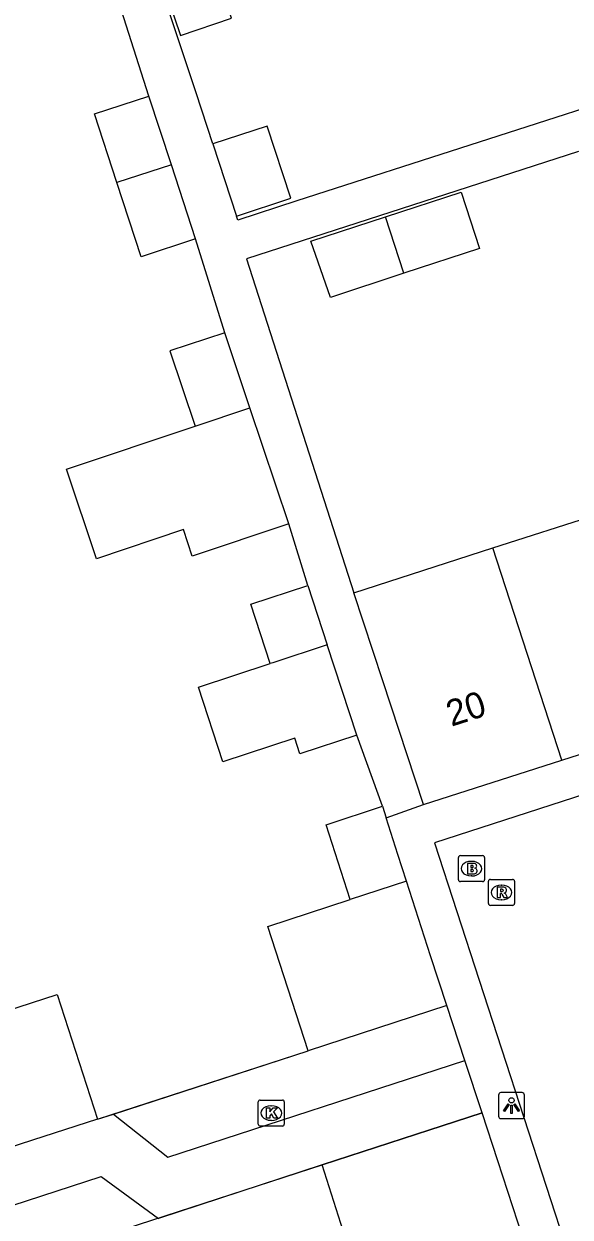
# Model space of a CAD drawing. Extents: x 159377 to 159983, y 382996 to 383595.
# Drawn here: x 159478 to 159498.96, y 383184.26 to 383230.07 of the extents above; entities that cross this region are included whole.
import ezdxf

# ---------------------------------------------------------------- set-up
doc = ezdxf.new("R2010")
doc.units = 0
for name, color, linetype in [('IMGEO_Brandkraan', 7, 'Continuous'), ('IMGEO_Groenvoorziening', 7, 'Continuous'), ('IMGEO_Kolk', 7, 'Continuous'), ('IMGEO_Lichtpunt', 7, 'Continuous'), ('IMGEO_Muur', 7, 'Continuous'), ('IMGEO_Pand', 7, 'Continuous'), ('IMGEO_Pand_nummerreeks', 7, 'Continuous'), ('IMGEO_Rijbaan_lokaal_open', 7, 'Continuous'), ('IMGEO_Rioolput', 7, 'Continuous'), ('IMGEO_Voetpad_open', 7, 'Continuous')]:
    doc.layers.add(name, color=color, linetype=linetype)

msp = doc.modelspace()

# ---------------------------------------------------------------- linework, layer by layer
at = {"layer": 'IMGEO_Brandkraan'}
for p, q in [((159494.749, 383198.14), (159495.601, 383198.14)), ((159494.674, 383197.214), (159494.674, 383198.066)), ((159495.162, 383197.92), (159495.187, 383197.92)), ((159495.675, 383198.066), (159495.675, 383197.214)), ((159495.185, 383197.36), (159495.16, 383197.36)), ((159495.601, 383197.14), (159494.749, 383197.14))]:
    msp.add_line(p, q, dxfattribs=at)
for points in [[(159494.749, 383198.14), (159495.601, 383198.14)], [(159494.674, 383197.214), (159494.674, 383198.066)], [(159495.022, 383197.84), (159495.022, 383197.44), (159495.235, 383197.44)], [(159495.253, 383197.84), (159495.022, 383197.84)], [(159495.201, 383197.759), (159495.147, 383197.759), (159495.147, 383197.683)], [(159495.147, 383197.683), (159495.2, 383197.683)], [(159495.675, 383198.066), (159495.675, 383197.214)], [(159495.209, 383197.607), (159495.147, 383197.607), (159495.147, 383197.526)], [(159495.147, 383197.526), (159495.209, 383197.526)], [(159495.601, 383197.14), (159494.749, 383197.14)]]:
    msp.add_lwpolyline(points, dxfattribs=at)
for centre, radius, start, end in [((159494.751, 383198.064), 0.0765, 91.552, 178.448), ((159494.751, 383198.064), 0.0765, 91.552, 178.448), ((159495.599, 383198.064), 0.0765, 1.552, 88.448), ((159495.599, 383198.064), 0.0765, 1.552, 88.448), ((159495.202, 383197.721), 0.0379, 267.8285, 90.9355), ((159495.257, 383197.695), 0.145, 59.4692, 91.5367), ((159495.282, 383197.742), 0.0922, 285.5137, 58.1501), ((159495.21, 383197.566), 0.0404, 269.8759, 90.5077), ((159495.241, 383197.691), 0.251, 268.6676, 293.5347), ((159495.287, 383197.55), 0.105, 301.3115, 78.989), ((159494.751, 383197.216), 0.0765, 181.552, 268.448), ((159494.751, 383197.216), 0.0765, 181.552, 268.448), ((159495.599, 383197.216), 0.0765, 271.552, 358.448), ((159495.599, 383197.216), 0.0765, 271.552, 358.448)]:
    msp.add_arc(centre, radius, start, end, dxfattribs=at)
for centre, major_axis, ratio, start_param, end_param in [((159495.161, 383197.64), (-0.387, 0.002), 0.722429, 4.712389, 7.853982), ((159495.186, 383197.64), (-0.39, 0.002), 0.717154, 1.570796, 4.712389)]:
    msp.add_ellipse(centre, major_axis=major_axis, ratio=ratio, start_param=start_param, end_param=end_param, dxfattribs=at)
at = {"layer": 'IMGEO_Groenvoorziening'}
msp.add_lwpolyline([(159481.432, 383188.219), (159488.903, 383190.64)], dxfattribs=at)
at = {"layer": 'IMGEO_Kolk'}
for p, q in [((159486.991, 383187.83), (159486.991, 383188.682)), ((159487.066, 383188.756), (159487.918, 383188.756)), ((159487.479, 383188.536), (159487.504, 383188.536)), ((159487.992, 383188.682), (159487.992, 383187.83)), ((159487.918, 383187.756), (159487.066, 383187.756)), ((159487.502, 383187.976), (159487.477, 383187.976))]:
    msp.add_line(p, q, dxfattribs=at)
for points in [[(159486.991, 383187.83), (159486.991, 383188.682)], [(159487.066, 383188.756), (159487.918, 383188.756)], [(159487.992, 383188.682), (159487.992, 383187.83)], [(159487.312, 383188.456), (159487.435, 383188.456), (159487.435, 383188.305), (159487.565, 383188.456), (159487.729, 383188.456), (159487.583, 383188.305), (159487.736, 383188.056), (159487.584, 383188.056), (159487.499, 383188.22), (159487.435, 383188.153), (159487.435, 383188.056), (159487.312, 383188.056), (159487.312, 383188.456)], [(159487.918, 383187.756), (159487.066, 383187.756)]]:
    msp.add_lwpolyline(points, dxfattribs=at)
for centre, start, end in [((159487.068, 383188.68), 91.552, 178.448), ((159487.068, 383188.68), 91.552, 178.448), ((159487.916, 383188.68), 1.552, 88.448), ((159487.916, 383188.68), 1.552, 88.448), ((159487.068, 383187.832), 181.552, 268.448), ((159487.068, 383187.832), 181.552, 268.448), ((159487.916, 383187.832), 271.552, 358.448), ((159487.916, 383187.832), 271.552, 358.448)]:
    msp.add_arc(centre, 0.0765, start, end, dxfattribs=at)
for centre, major_axis, ratio, start_param, end_param in [((159487.478, 383188.256), (-0.387, 0.002), 0.722429, 4.712389, 7.853982), ((159487.503, 383188.256), (-0.39, 0.002), 0.717154, 1.570796, 4.712389)]:
    msp.add_ellipse(centre, major_axis=major_axis, ratio=ratio, start_param=start_param, end_param=end_param, dxfattribs=at)
at = {"layer": 'IMGEO_Lichtpunt'}
for p, q in [((159497.113, 383189.041), (159496.305, 383189.041)), ((159497.113, 383189.041), (159496.305, 383189.041)), ((159496.211, 383188.946), (159496.211, 383188.139)), ((159496.211, 383188.946), (159496.211, 383188.139)), ((159497.207, 383188.139), (159497.207, 383188.946)), ((159497.207, 383188.139), (159497.207, 383188.946)), ((159496.305, 383188.045), (159497.113, 383188.045)), ((159496.305, 383188.045), (159497.113, 383188.045))]:
    msp.add_line(p, q, dxfattribs=at)
for points in [[(159496.585, 383188.61), (159496.624, 383188.582), (159496.436, 383188.32), (159496.398, 383188.347), (159496.585, 383188.61)], [(159496.687, 383188.562), (159496.734, 383188.562), (159496.734, 383188.24), (159496.687, 383188.24), (159496.687, 383188.562)], [(159496.797, 383188.582), (159496.835, 383188.609), (159497.022, 383188.347), (159496.983, 383188.319), (159496.797, 383188.582)]]:
    msp.add_lwpolyline(points, dxfattribs=at)
msp.add_circle((159496.71, 383188.744), 0.0994, dxfattribs=at)
for centre, start, end in [((159496.305, 383188.946), 90, 180), ((159496.305, 383188.946), 90, 180), ((159497.113, 383188.946), 0, 90), ((159497.113, 383188.946), 0, 90), ((159496.305, 383188.139), 180, 270), ((159496.305, 383188.139), 180, 270), ((159497.113, 383188.139), 270, 0), ((159497.113, 383188.139), 270, 360)]:
    msp.add_arc(centre, 0.0946, start, end, dxfattribs=at)
at = {"layer": 'IMGEO_Muur'}
for points in [[(159480.817, 383188.02), (159488.903, 383190.64)], [(159479.701, 383183.1), (159482.401, 383183.978), (159495.589, 383188.265)]]:
    msp.add_lwpolyline(points, dxfattribs=at)
at = {"layer": 'IMGEO_Pand'}
for points in [[(159482.871, 383232.987), (159484.01, 383229.627), (159485.967, 383230.29), (159484.837, 383233.623)], [(159481.567, 383223.976), (159480.704, 383226.615), (159482.795, 383227.299)], [(159483.659, 383224.654), (159482.795, 383227.299)], [(159486.157, 383222.692), (159488.238, 383223.375), (159487.33, 383226.144), (159485.248, 383225.462)], [(159485.248, 383225.462), (159486.157, 383222.692)], [(159483.659, 383224.654), (159481.567, 383223.976)], [(159484.587, 383221.813), (159483.659, 383224.654)], [(159484.587, 383221.813), (159482.497, 383221.131), (159481.567, 383223.976)], [(159491.878, 383222.663), (159494.778, 383223.614), (159495.481, 383221.446), (159492.581, 383220.495)], [(159492.581, 383220.495), (159489.763, 383219.571), (159489.015, 383221.724), (159491.878, 383222.663)], [(159492.581, 383220.495), (159491.878, 383222.663)], [(159485.703, 383218.216), (159483.604, 383217.513), (159484.57, 383214.627)], [(159486.67, 383215.33), (159485.703, 383218.216)], [(159484.57, 383214.627), (159486.67, 383215.33)], [(159488.161, 383210.876), (159486.67, 383215.33)], [(159488.161, 383210.876), (159484.461, 383209.638), (159484.12, 383210.655), (159480.784, 383209.538), (159479.633, 383212.974), (159484.57, 383214.627)], [(159495.999, 383209.952), (159500, 383211.241), (159501.129, 383211.604)], [(159490.664, 383208.234), (159495.999, 383209.952)], [(159498.642, 383201.8), (159495.999, 383209.952)], [(159487.453, 383205.513), (159486.706, 383207.787), (159488.894, 383208.506)], [(159488.894, 383208.506), (159489.641, 383206.231)], [(159493.339, 383200.096), (159491.778, 383204.846), (159490.664, 383208.234)], [(159489.641, 383206.231), (159487.545, 383205.542), (159487.453, 383205.513)], [(159490.78, 383202.765), (159489.641, 383206.231)], [(159490.78, 383202.765), (159488.592, 383202.046), (159488.395, 383202.646), (159485.637, 383201.74), (159484.695, 383204.606), (159487.453, 383205.513)], [(159498.642, 383201.8), (159500, 383202.236), (159503.773, 383203.448)], [(159493.339, 383200.096), (159498.642, 383201.8)], [(159490.525, 383196.453), (159489.601, 383199.327), (159491.758, 383200.033)], [(159491.758, 383200.033), (159491.9, 383199.592)], [(159492.685, 383197.153), (159492.353, 383198.185), (159491.9, 383199.592)], [(159492.685, 383197.153), (159490.525, 383196.453)], [(159494.222, 383192.386), (159493.605, 383194.291), (159492.685, 383197.153)], [(159488.903, 383190.64), (159487.357, 383195.413), (159490.525, 383196.453)], [(159476.779, 383191.997), (159479.269, 383192.804), (159480.817, 383188.02)], [(159494.222, 383192.386), (159488.903, 383190.64)], [(159495.589, 383188.265), (159489.44, 383186.266)], [(159497.142, 383183.482), (159496.188, 383186.42), (159495.589, 383188.265)], [(159480.817, 383188.02), (159478.331, 383187.21), (159469.497, 383184.351)], [(159494.955, 383182.771), (159490.967, 383181.485), (159489.44, 383186.266)]]:
    msp.add_lwpolyline(points, dxfattribs=at)
at = {"layer": 'IMGEO_Rijbaan_lokaal_open'}
msp.add_lwpolyline([(159520.354, 383207.214), (159514.946, 383205.47), (159500, 383200.651), (159493.749, 383198.635), (159499.75, 383180.18), (159500, 383180.243), (159536.251, 383191.843)], dxfattribs=at)
at = {"layer": 'IMGEO_Rioolput'}
for p, q in [((159495.899, 383197.227), (159496.751, 383197.227)), ((159495.824, 383196.301), (159495.824, 383197.153)), ((159496.312, 383197.007), (159496.337, 383197.007)), ((159496.825, 383197.153), (159496.825, 383196.301)), ((159496.335, 383196.447), (159496.31, 383196.447)), ((159496.751, 383196.227), (159495.899, 383196.227))]:
    msp.add_line(p, q, dxfattribs=at)
for points in [[(159495.899, 383197.227), (159496.751, 383197.227)], [(159495.824, 383196.301), (159495.824, 383197.153)], [(159496.413, 383196.925), (159496.161, 383196.927), (159496.161, 383196.527)], [(159496.339, 383196.846), (159496.285, 383196.846), (159496.285, 383196.765)], [(159496.285, 383196.765), (159496.337, 383196.765)], [(159496.825, 383197.153), (159496.825, 383196.301)], [(159496.161, 383196.527), (159496.285, 383196.527), (159496.285, 383196.689), (159496.296, 383196.689)], [(159496.343, 383196.66), (159496.414, 383196.527), (159496.554, 383196.527), (159496.489, 383196.653)], [(159496.751, 383196.227), (159495.899, 383196.227)]]:
    msp.add_lwpolyline(points, dxfattribs=at)
for centre, radius, start, end in [((159495.901, 383197.151), 0.0765, 91.552, 178.448), ((159495.901, 383197.151), 0.0765, 91.552, 178.448), ((159496.749, 383197.151), 0.0765, 1.552, 88.448), ((159496.749, 383197.151), 0.0765, 1.552, 88.448), ((159496.321, 383196.954), 0.19, 274.7715, 282.9687), ((159496.345, 383196.75), 0.0964, 77.0061, 93.1865), ((159496.359, 383196.807), 0.0378, 276.6634, 79.6772), ((159496.412, 383196.815), 0.109, 350.3612, 89.416), ((159496.41, 383196.815), 0.112, 277.5842, 350.9817), ((159496.295, 383196.636), 0.0533, 26.0293, 88.6989), ((159496.394, 383196.6), 0.108, 29.5134, 73.7905), ((159495.901, 383196.303), 0.0765, 181.552, 268.448), ((159495.901, 383196.303), 0.0765, 181.552, 268.448), ((159496.749, 383196.303), 0.0765, 271.552, 358.448), ((159496.749, 383196.303), 0.0765, 271.552, 358.448)]:
    msp.add_arc(centre, radius, start, end, dxfattribs=at)
for centre, major_axis, ratio, start_param, end_param in [((159496.311, 383196.727), (-0.387, 0.002), 0.722429, 4.712389, 7.853982), ((159496.336, 383196.727), (-0.39, 0.002), 0.717154, 1.570796, 4.712389)]:
    msp.add_ellipse(centre, major_axis=major_axis, ratio=ratio, start_param=start_param, end_param=end_param, dxfattribs=at)
at = {"layer": 'IMGEO_Voetpad_open'}
for points in [[(159485.248, 383225.462), (159484.606, 383227.42), (159474.303, 383258.392), (159471.815, 383257.591)], [(159482.795, 383227.299), (159481.642, 383230.906)], [(159502.462, 383227.783), (159488.475, 383223.275), (159486.209, 383222.532), (159486.157, 383222.692)], [(159499.277, 383225.177), (159486.536, 383221.053), (159490.664, 383208.234)], [(159485.703, 383218.216), (159484.587, 383221.813)], [(159488.894, 383208.506), (159488.161, 383210.876)], [(159491.758, 383200.033), (159490.78, 383202.765)], [(159491.9, 383199.592), (159493.339, 383200.096)], [(159494.924, 383190.271), (159494.222, 383192.386)], [(159481.432, 383188.219), (159483.517, 383186.567), (159494.924, 383190.271)], [(159495.589, 383188.265), (159494.924, 383190.271)], [(159480.817, 383188.02), (159481.432, 383188.219)], [(159489.44, 383186.266), (159483.158, 383184.208)], [(159470.835, 383180.219), (159470.155, 383182.307), (159480.969, 383185.822), (159483.158, 383184.208)]]:
    msp.add_lwpolyline(points, dxfattribs=at)

# ---------------------------------------------------------------- texts
at = {"layer": 'IMGEO_Pand_nummerreeks'}
msp.add_text('20', height=1, rotation=17.8128, dxfattribs=at).set_placement((159494.401, 383203.084))

doc.saveas('drawing.dxf')
